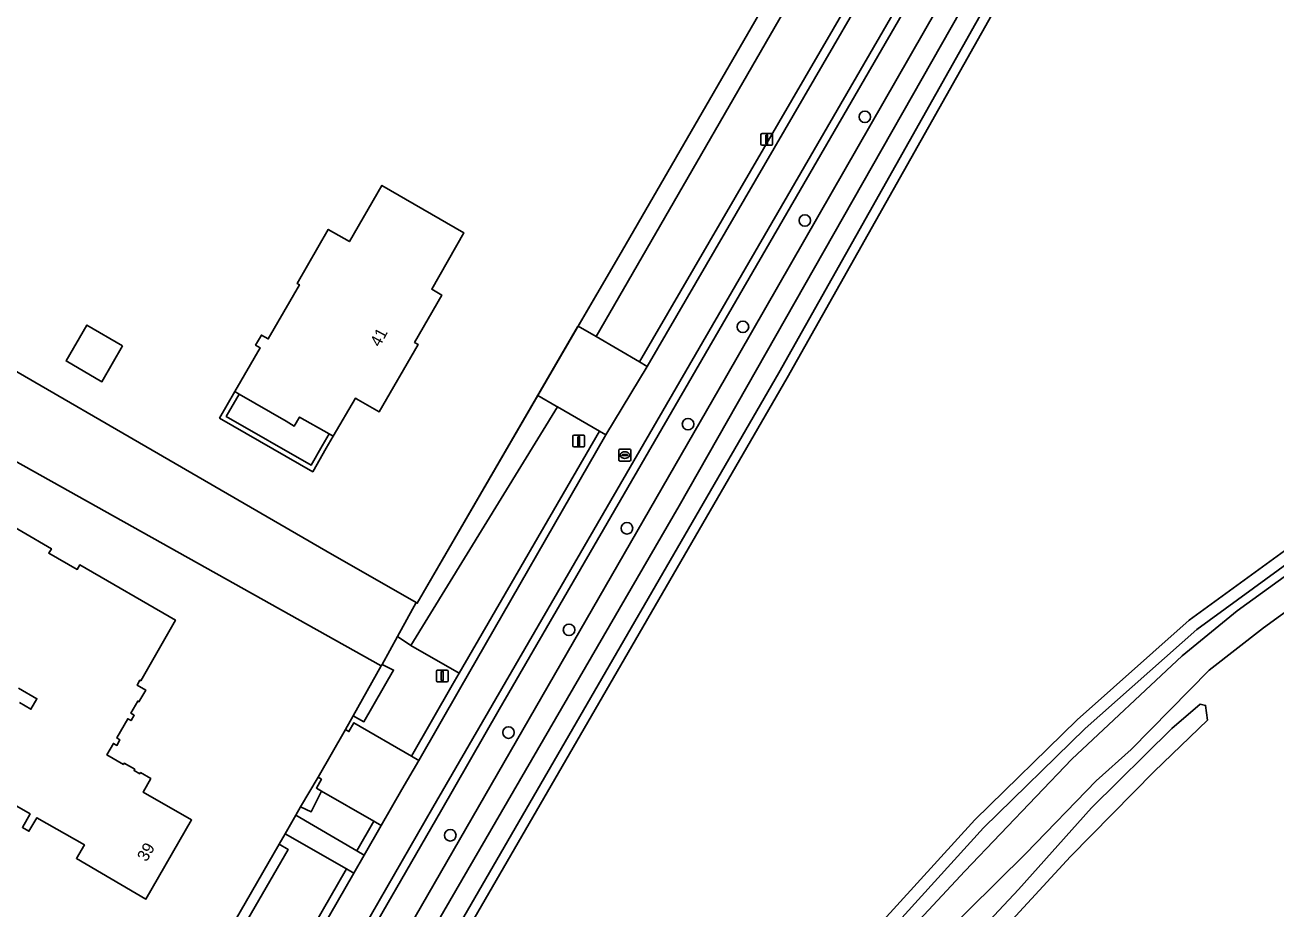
# Model space of a CAD drawing. Extents: x 156502 to 159075, y 384229 to 386100.
# Drawn here: x 157270.5 to 157376.3, y 385705.1 to 385779.8 of the extents above; entities that cross this region are included whole.
import ezdxf

# ---------------------------------------------------------------- set-up
doc = ezdxf.new("R2010")
doc.units = 0
for name, color, linetype in [('IMGEO_Boom', 7, 'Continuous'), ('IMGEO_Erf', 7, 'Continuous'), ('IMGEO_Gemengd_bos', 7, 'Continuous'), ('IMGEO_Grasland_overig', 7, 'Continuous'), ('IMGEO_Greppel_droge_sloot', 7, 'Continuous'), ('IMGEO_Groenvoorziening', 7, 'Continuous'), ('IMGEO_Hek', 7, 'Continuous'), ('IMGEO_Lichtmast', 7, 'Continuous'), ('IMGEO_Muur', 7, 'Continuous'), ('IMGEO_Oever', 7, 'Continuous'), ('IMGEO_Pand', 7, 'Continuous'), ('IMGEO_Pand_nummerreeks', 7, 'Continuous'), ('IMGEO_Rijbaan_lokaal_halfverhard', 7, 'Continuous'), ('IMGEO_Rijbaan_lokaal_onverhard', 7, 'Continuous'), ('IMGEO_Rijbaan_lokaal_open', 7, 'Continuous'), ('IMGEO_Rioolput', 7, 'Continuous'), ('IMGEO_Voetpad_open', 7, 'Continuous'), ('IMGEO_Waterloop', 7, 'Continuous')]:
    doc.layers.add(name, color=color, linetype=linetype)

msp = doc.modelspace()

# ---------------------------------------------------------------- linework, layer by layer
at = {"layer": 'IMGEO_Boom'}
for centre in [(157341.53, 385772.07), (157336.45, 385763.3), (157331.21, 385754.3), (157326.57, 385746.07), (157321.4, 385737.26), (157316.5, 385728.67), (157311.38, 385719.98), (157306.45, 385711.29)]:
    msp.add_circle(centre, 0.489, dxfattribs=at)
at = {"layer": 'IMGEO_Erf'}
for points in [[(157260.44, 385826.72), (157272.04, 385820.04), (157275.52, 385818.05), (157285.22, 385812.46), (157254.63, 385759.26), (157295.91, 385735.36), (157303.57, 385730.97), (157303.66, 385730.92), (157313.86, 385748.5), (157317.18, 385754.23), (157317.26, 385754.36), (157320.72, 385760.25), (157337.11, 385788.6), (157340.4, 385794.34), (157345.49, 385803.19), (157347.71, 385807.02), (157370.69, 385846.65), (157370.74, 385846.77), (157371.55, 385848.55), (157374.53, 385855.11), (157336.95, 385876.45)], [(157268.67, 385670.14), (157291.96, 385710.53), (157292.48, 385711.42), (157293.37, 385712.99), (157293.78, 385713.69), (157295.26, 385716.2), (157297.59, 385720.23), (157298.24, 385721.4), (157300.61, 385725.63), (157250.89, 385753.43)], [(157267.66, 385738.45), (157272.7, 385735.53), (157272.48, 385735.15), (157274.88, 385733.78), (157275.1, 385734.16), (157283.19, 385729.49), (157280.26, 385724.37), (157280.18, 385724.41), (157279.95, 385724), (157280.68, 385723.58), (157280.11, 385722.58), (157280.01, 385722.64), (157279.42, 385721.62), (157279.71, 385721.45), (157279.44, 385720.99), (157279.16, 385721.15), (157278.23, 385719.52), (157278.5, 385719.36), (157278.24, 385718.89), (157277.95, 385719.06), (157277.39, 385718.09), (157278.79, 385717.29), (157278.85, 385717.39), (157279.75, 385716.87), (157279.69, 385716.77), (157280.18, 385716.49), (157280.24, 385716.59), (157281.11, 385716.09), (157280.46, 385714.94), (157284.56, 385712.59), (157280.7, 385705.9), (157274.81, 385709.33), (157275.49, 385710.48), (157271.47, 385712.78), (157270.8, 385711.63), (157270.24, 385711.96), (157270.9, 385713.1), (157266.2, 385715.79)], [(157270, 385722.51), (157270.96, 385721.95), (157271.48, 385722.84), (157269.92, 385723.74)]]:
    msp.add_lwpolyline(points, dxfattribs=at)
for points in [[(157290.36, 385752.54), (157289.98, 385752.76), (157290.47, 385753.61), (157291.05, 385753.28), (157293.69, 385757.86), (157293.49, 385757.98), (157296.12, 385762.54), (157297.92, 385761.51), (157300.66, 385766.27), (157307.61, 385762.25), (157304.88, 385757.48), (157305.73, 385756.99), (157303.43, 385752.99), (157303.72, 385752.82), (157300.42, 385747.11), (157298.66, 385748.13), (157298.42, 385748.26), (157296.54, 385745.04), (157295.96, 385744.03), (157294.81, 385742.04), (157286.93, 385746.58), (157288.22, 385748.82)], [(157278.72, 385752.69), (157276.97, 385749.66), (157273.94, 385751.42), (157275.7, 385754.45)], [(157287.5, 385746.73), (157294.67, 385742.59), (157295.61, 385744.23), (157296.19, 385745.24), (157293.7, 385746.67), (157293.25, 385745.91), (157292.55, 385746.32), (157288.58, 385748.61)]]:
    msp.add_lwpolyline(points, close=True, dxfattribs=at)
at = {"layer": 'IMGEO_Gemengd_bos'}
for points in [[(157458.7, 385822.57), (157423.67, 385843.01), (157401.01, 385856.04), (157400.45, 385856.36), (157400.33, 385856.13), (157400.02, 385856.3), (157396.13, 385858.5), (157395.47, 385857.33), (157372.59, 385816.74), (157334.96, 385750), (157287.88, 385668.68), (157271.39, 385640.19), (157191.03, 385500)], [(157313.88, 385657.2), (157319.42, 385669.46), (157326.38, 385682.33), (157329.75, 385687.46), (157336.36, 385696.35), (157342.79, 385703.77), (157350.84, 385712.61), (157359.49, 385721.05), (157368.98, 385729.49), (157384.16, 385740.55), (157398.32, 385750), (157403.23, 385753.28), (157414.47, 385760.23), (157425.48, 385766.09), (157436.74, 385770.62), (157451.12, 385774.84), (157465.72, 385778.54), (157474.31, 385780.52)], [(157474.54, 385779.54), (157465.96, 385777.56), (157451.38, 385773.86), (157437.07, 385769.66), (157425.91, 385765.18), (157414.97, 385759.35), (157403.77, 385752.43), (157400.13, 385750), (157384.74, 385739.73), (157369.61, 385728.71), (157360.18, 385720.32), (157351.57, 385711.91), (157343.55, 385703.1), (157337.15, 385695.72), (157330.58, 385686.89), (157327.25, 385681.81), (157320.32, 385669.01), (157314.81, 385656.81), (157309.55, 385643.22), (157304.76, 385626.85), (157289.94, 385563.14), (157287.02, 385552.69)], [(157307.36, 385633.66), (157308.77, 385638.36), (157313.72, 385652.7), (157315.99, 385658.02), (157324.09, 385675.08), (157328.32, 385682.73), (157330.69, 385686.32), (157335.38, 385692.58), (157350, 385708.26), (157359.05, 385717.74), (157368.37, 385726.47), (157373.02, 385730.27), (157388.24, 385741.27), (157401.41, 385750), (157406.16, 385753.14), (157410.79, 385755.97), (157420.02, 385761.13), (157420.89, 385761.55), (157433.84, 385766.77), (157439.68, 385768.72), (157452.62, 385772.03)]]:
    msp.add_lwpolyline(points, dxfattribs=at)
msp.add_lwpolyline([(157285.22, 385812.46), (157275.52, 385818.05), (157272.04, 385820.04), (157246.93, 385776.79), (157242.96, 385769.96), (157222.97, 385734.27), (157232.44, 385728.12), (157250.89, 385753.43), (157300.61, 385725.63), (157300.68, 385725.75), (157301.99, 385728.11), (157303.57, 385730.97), (157295.91, 385735.36), (157254.63, 385759.26)], close=True, dxfattribs=at)
at = {"layer": 'IMGEO_Grasland_overig'}
for points in [[(157385.01, 385735.91), (157375.26, 385728.85), (157370.65, 385725.25), (157364.06, 385718.55), (157361.1, 385715.9), (157355.14, 385709.74), (157340.46, 385695.22), (157338.44, 385692.86), (157335.57, 385689), (157332.67, 385684.44), (157330.34, 385679.68), (157328.02, 385675.4), (157323.45, 385668.06), (157321.88, 385665.22), (157317.27, 385655), (157315.24, 385649.68), (157313.24, 385643.86), (157311.39, 385637.62), (157309.76, 385633.05)], [(157320.16, 385654.3), (157326.49, 385667.85), (157329.13, 385673.02), (157336.2, 385684.73), (157342.72, 385693.77), (157347.46, 385699.15), (157354.54, 385706.7), (157360.71, 385713.62), (157367.5, 385720.32), (157369.9, 385722.39), (157370.36, 385722.27), (157370.53, 385721.03), (157366.02, 385716.7), (157358.94, 385709.5), (157353.97, 385704.1), (157342.4, 385690.74)]]:
    msp.add_lwpolyline(points, dxfattribs=at)
at = {"layer": 'IMGEO_Greppel_droge_sloot'}
for points in [[(157393.36, 385858.05), (157393.11, 385857.61), (157362.75, 385804.11), (157325.82, 385739.17), (157293.92, 385684.22), (157277.51, 385655.56), (157259.26, 385623.71), (157238.62, 385587.75), (157224.85, 385563.79), (157203.07, 385525.9), (157174.27, 385475.36), (157161.25, 385452.05), (157151.08, 385433.93), (157146.7, 385427.27), (157144.86, 385424.97)], [(157146.46, 385424.36), (157148.98, 385428.05), (157150.58, 385430.99), (157151.89, 385433.4), (157190.31, 385500.41), (157270.67, 385640.6), (157287.16, 385669.09), (157334.24, 385750.41), (157371.86, 385817.15), (157394.6, 385857.47)]]:
    msp.add_lwpolyline(points, dxfattribs=at)
at = {"layer": 'IMGEO_Groenvoorziening'}
for points in [[(157395.47, 385857.33), (157396.13, 385858.5), (157400.02, 385856.3), (157400.33, 385856.13), (157400.45, 385856.36), (157394.87, 385860.03), (157394.47, 385860.19), (157394.07, 385860.35), (157391.83, 385861.67), (157349.52, 385789.09), (157310.6, 385721.93), (157305.61, 385713.27), (157297.81, 385699.74), (157287.9, 385682.57), (157281.97, 385672.23), (157284.2, 385670.89), (157329.73, 385750)], [(157329.73, 385750), (157392.25, 385858.97)]]:
    msp.add_lwpolyline(points, dxfattribs=at)
for points in [[(157338.56, 385787.75), (157337.11, 385788.6), (157320.72, 385760.25), (157317.26, 385754.36), (157318.78, 385753.48)], [(157342.35, 385785.53), (157338.56, 385787.75), (157318.78, 385753.48), (157322.45, 385751.34)], [(157315.53, 385747.53), (157315.4, 385747.6), (157313.86, 385748.5), (157303.66, 385730.92), (157303.57, 385730.97), (157301.99, 385728.11), (157303.1, 385727.35)], [(157319.08, 385745.47), (157315.53, 385747.53), (157303.1, 385727.35), (157307.21, 385725.01)], [(157306.6, 385723.98), (157307.21, 385725.01), (157303.1, 385727.35), (157301.99, 385728.11), (157300.68, 385725.75), (157301.65, 385725.27), (157299.14, 385720.9), (157298.24, 385721.4), (157297.59, 385720.23), (157297.87, 385720.06), (157298.3, 385720.81), (157303.16, 385717.99)], [(157300.68, 385725.75), (157300.61, 385725.63), (157298.24, 385721.4), (157299.14, 385720.9), (157301.65, 385725.27)], [(157295.56, 385715.03), (157295.12, 385715.29), (157295.54, 385716.03), (157295.26, 385716.2), (157293.78, 385713.69), (157294.67, 385713.27)], [(157295.56, 385715.03), (157294.67, 385713.27), (157293.78, 385713.69), (157293.37, 385712.99), (157298.55, 385709.98), (157299.99, 385712.48)], [(157293.66, 385701.48), (157297.66, 385708.44), (157292.48, 385711.42), (157291.96, 385710.53), (157292.73, 385710.1), (157269.35, 385669.72), (157270.11, 385669.25), (157268.64, 385666.52), (157272.3, 385664.39), (157273.57, 385666.58), (157284.33, 385685.27)], [(157291.96, 385710.53), (157268.67, 385670.14), (157269.35, 385669.72), (157292.73, 385710.1)]]:
    msp.add_lwpolyline(points, close=True, dxfattribs=at)
at = {"layer": 'IMGEO_Hek'}
for points in [[(157334.96, 385750), (157372.59, 385816.74)], [(157295.91, 385735.36), (157254.63, 385759.26), (157285.22, 385812.46)], [(157320.72, 385760.25), (157337.11, 385788.6)], [(157320.72, 385760.25), (157317.18, 385754.23)], [(157303.57, 385730.97), (157303.66, 385730.92), (157317.21, 385754.31)], [(157334.96, 385750), (157287.88, 385668.68)], [(157295.91, 385735.36), (157303.57, 385730.97)]]:
    msp.add_lwpolyline(points, dxfattribs=at)
at = {"layer": 'IMGEO_Lichtmast'}
for p, q in [((157332.73, 385769.76), (157332.73, 385770.55)), ((157332.73, 385770.55), (157332.73, 385769.76)), ((157332.83, 385770.65), (157333.62, 385770.65)), ((157333.62, 385770.65), (157332.83, 385770.65)), ((157333.72, 385770.55), (157333.72, 385769.76)), ((157333.72, 385769.76), (157333.72, 385770.55)), ((157333.62, 385769.66), (157332.83, 385769.66)), ((157332.83, 385769.66), (157333.62, 385769.66)), ((157316.82, 385744.24), (157316.82, 385745.04)), ((157316.82, 385745.04), (157316.82, 385744.24)), ((157316.92, 385745.14), (157317.71, 385745.14)), ((157317.71, 385745.14), (157316.92, 385745.14)), ((157317.81, 385745.04), (157317.81, 385744.24)), ((157317.81, 385744.24), (157317.81, 385745.04)), ((157317.71, 385744.14), (157316.92, 385744.14)), ((157316.92, 385744.14), (157317.71, 385744.14)), ((157305.38, 385725.27), (157306.16, 385725.27)), ((157306.16, 385725.27), (157305.38, 385725.27)), ((157305.28, 385724.37), (157305.28, 385725.17)), ((157305.28, 385725.17), (157305.28, 385724.37)), ((157306.16, 385724.27), (157305.38, 385724.27)), ((157305.38, 385724.27), (157306.16, 385724.27)), ((157306.26, 385725.17), (157306.26, 385724.37)), ((157306.26, 385724.37), (157306.26, 385725.17))]:
    msp.add_line(p, q, dxfattribs=at)
for points in [[(157333.15, 385770.53), (157333.3, 385770.53), (157333.3, 385769.78), (157333.15, 385769.78), (157333.15, 385770.53)], [(157317.24, 385745.01), (157317.39, 385745.01), (157317.39, 385744.26), (157317.24, 385744.26), (157317.24, 385745.01)], [(157305.69, 385725.14), (157305.85, 385725.14), (157305.85, 385724.39), (157305.69, 385724.39), (157305.69, 385725.14)]]:
    msp.add_lwpolyline(points, dxfattribs=at)
for centre, start, end in [((157332.83, 385770.55), 90, 180), ((157332.83, 385770.55), 90, 180), ((157332.83, 385769.76), 180, 270), ((157332.83, 385769.76), 180, 270), ((157333.62, 385770.55), 0, 90), ((157333.62, 385770.55), 360, 90), ((157333.62, 385769.76), 270, 0), ((157333.62, 385769.76), 270, 0), ((157316.92, 385745.04), 90, 180), ((157316.92, 385745.04), 90, 180), ((157317.71, 385745.04), 0, 90), ((157317.71, 385745.04), 360, 90), ((157316.92, 385744.24), 180, 270), ((157316.92, 385744.24), 180, 270), ((157317.71, 385744.24), 270, 0), ((157317.71, 385744.24), 270, 0), ((157305.38, 385725.17), 90, 180), ((157305.38, 385725.17), 90, 180), ((157306.16, 385725.17), 0, 90), ((157306.16, 385725.17), 360, 90), ((157305.38, 385724.37), 180, 270), ((157305.38, 385724.37), 180, 270), ((157306.16, 385724.37), 270, 0), ((157306.16, 385724.37), 270, 0)]:
    msp.add_arc(centre, 0.1, start, end, dxfattribs=at)
at = {"layer": 'IMGEO_Muur'}
msp.add_lwpolyline([(157286.93, 385746.58), (157294.81, 385742.04), (157295.96, 385744.03), (157296.54, 385745.04), (157296.19, 385745.24), (157295.61, 385744.23), (157294.67, 385742.59), (157287.5, 385746.73), (157288.58, 385748.61), (157288.22, 385748.82)], close=True, dxfattribs=at)
at = {"layer": 'IMGEO_Oever'}
for points in [[(157392.25, 385858.97), (157329.73, 385750), (157284.2, 385670.89), (157172.1, 385476.13), (157169.19, 385471.06), (157144.41, 385428.01), (157142.39, 385426.07), (157140.63, 385424.94), (157139.2, 385424.57), (157138.03, 385424.77), (157136.95, 385425.17), (157066.81, 385467.26), (157031.92, 385488.2), (156971.45, 385524.49), (156960.96, 385531.06), (156958.28, 385532.65)], [(157144.86, 385424.97), (157146.7, 385427.27), (157151.08, 385433.93), (157161.25, 385452.05), (157174.27, 385475.36), (157203.07, 385525.9), (157224.85, 385563.79), (157238.62, 385587.75), (157259.26, 385623.71), (157277.51, 385655.56), (157293.92, 385684.22), (157325.82, 385739.17), (157362.75, 385804.11), (157393.11, 385857.61), (157393.36, 385858.05)], [(157146.17, 385421.74), (157150.67, 385429.59), (157152.55, 385432.88), (157191.03, 385500), (157271.39, 385640.19), (157287.88, 385668.68), (157334.96, 385750), (157372.59, 385816.74), (157395.47, 385857.33)], [(157394.6, 385857.47), (157371.86, 385817.15), (157334.24, 385750.41), (157287.16, 385669.09), (157270.67, 385640.6), (157190.31, 385500.41), (157151.89, 385433.4), (157150.58, 385430.99), (157148.98, 385428.05), (157146.46, 385424.36)]]:
    msp.add_lwpolyline(points, dxfattribs=at)
at = {"layer": 'IMGEO_Pand'}
for points in [[(157293.49, 385757.98), (157293.69, 385757.86), (157291.05, 385753.28), (157290.47, 385753.61), (157289.98, 385752.76), (157290.36, 385752.54), (157288.22, 385748.82), (157288.58, 385748.61), (157292.55, 385746.32), (157293.25, 385745.91), (157293.7, 385746.67), (157296.19, 385745.24), (157296.54, 385745.04), (157298.42, 385748.26), (157298.66, 385748.13), (157300.42, 385747.11), (157303.72, 385752.82), (157303.43, 385752.99), (157305.73, 385756.99), (157304.88, 385757.48), (157307.61, 385762.25), (157300.66, 385766.27), (157297.92, 385761.51), (157296.12, 385762.54)], [(157278.72, 385752.69), (157275.7, 385754.45), (157273.94, 385751.42), (157276.97, 385749.66)]]:
    msp.add_lwpolyline(points, close=True, dxfattribs=at)
for points in [[(157266.2, 385715.79), (157270.9, 385713.1), (157270.24, 385711.96), (157270.8, 385711.63), (157271.47, 385712.78), (157275.49, 385710.48), (157274.81, 385709.33), (157280.7, 385705.9), (157284.56, 385712.59), (157280.46, 385714.94), (157281.11, 385716.09), (157280.24, 385716.59), (157280.18, 385716.49), (157279.69, 385716.77), (157279.75, 385716.87), (157278.85, 385717.39), (157278.79, 385717.29), (157277.39, 385718.09), (157277.95, 385719.06), (157278.24, 385718.89), (157278.5, 385719.36), (157278.23, 385719.52), (157279.16, 385721.15), (157279.44, 385720.99), (157279.71, 385721.45), (157279.42, 385721.62), (157280.01, 385722.64), (157280.11, 385722.58), (157280.68, 385723.58), (157279.95, 385724), (157280.18, 385724.41), (157280.26, 385724.37), (157283.19, 385729.49), (157275.1, 385734.16), (157274.88, 385733.78), (157272.48, 385735.15), (157272.7, 385735.53), (157267.66, 385738.45)], [(157269.92, 385723.74), (157271.48, 385722.84), (157270.96, 385721.95), (157270, 385722.51)]]:
    msp.add_lwpolyline(points, dxfattribs=at)
at = {"layer": 'IMGEO_Rijbaan_lokaal_halfverhard'}
for points in [[(157349.52, 385789.09), (157348.91, 385789.44), (157309.98, 385722.29), (157304.98, 385713.63), (157297.19, 385700.1), (157287.28, 385682.93), (157276.98, 385664.99), (157272.99, 385658.15), (157259.7, 385634.92), (157260.02, 385634.73), (157260.32, 385634.56), (157273.62, 385657.79), (157277.6, 385664.64), (157281.97, 385672.23), (157287.9, 385682.57), (157297.81, 385699.74), (157305.61, 385713.27), (157310.6, 385721.93)], [(157342.98, 385785.16), (157342.35, 385785.53), (157322.45, 385751.34), (157323.12, 385750.95)], [(157319.61, 385745.16), (157319.08, 385745.47), (157307.21, 385725.01), (157306.6, 385723.98), (157303.16, 385717.99), (157303.78, 385717.63), (157307.23, 385723.61)], [(157300.61, 385712.13), (157299.99, 385712.48), (157298.55, 385709.98), (157299.17, 385709.62)], [(157298.29, 385708.09), (157297.66, 385708.44), (157293.66, 385701.48), (157284.33, 385685.27), (157273.57, 385666.58), (157272.3, 385664.39), (157272.92, 385664.02), (157274.19, 385666.22), (157284.95, 385684.91), (157294.28, 385701.12)]]:
    msp.add_lwpolyline(points, close=True, dxfattribs=at)
at = {"layer": 'IMGEO_Rijbaan_lokaal_onverhard'}
for points in [[(157452.62, 385772.03), (157439.68, 385768.72), (157433.84, 385766.77), (157420.89, 385761.55), (157420.02, 385761.13), (157410.79, 385755.97), (157406.16, 385753.14), (157401.41, 385750), (157388.24, 385741.27), (157373.02, 385730.27), (157368.37, 385726.47), (157359.05, 385717.74), (157350, 385708.26), (157335.38, 385692.58), (157330.69, 385686.32), (157328.32, 385682.73), (157324.09, 385675.08), (157315.99, 385658.02), (157313.72, 385652.7), (157308.77, 385638.36), (157307.36, 385633.66)], [(157309.76, 385633.05), (157311.39, 385637.62), (157313.24, 385643.86), (157315.24, 385649.68), (157317.27, 385655), (157321.88, 385665.22), (157323.45, 385668.06), (157328.02, 385675.4), (157330.34, 385679.68), (157332.67, 385684.44), (157335.57, 385689), (157338.44, 385692.86), (157340.46, 385695.22), (157355.14, 385709.74), (157361.1, 385715.9), (157364.06, 385718.55), (157370.65, 385725.25), (157375.26, 385728.85), (157385.01, 385735.91)]]:
    msp.add_lwpolyline(points, dxfattribs=at)
at = {"layer": 'IMGEO_Rijbaan_lokaal_open'}
for points in [[(157348.91, 385789.44), (157346.33, 385790.92), (157342.98, 385785.16), (157323.12, 385750.95), (157319.61, 385745.16), (157307.23, 385723.61), (157303.78, 385717.63), (157302.35, 385715.15), (157300.61, 385712.13), (157299.17, 385709.62), (157298.29, 385708.09), (157294.28, 385701.12), (157284.95, 385684.91), (157274.19, 385666.22), (157272.92, 385664.02), (157270.01, 385658.98), (157269.67, 385658.4), (157266.46, 385652.88), (157264.81, 385649.96)], [(157258.5, 385639.01), (157257.01, 385636.46), (157259.7, 385634.92), (157272.99, 385658.15), (157276.98, 385664.99), (157287.28, 385682.93), (157297.19, 385700.1), (157304.98, 385713.63), (157309.98, 385722.29), (157348.91, 385789.44)]]:
    msp.add_lwpolyline(points, dxfattribs=at)
for points in [[(157323.12, 385750.95), (157322.45, 385751.34), (157318.78, 385753.48), (157317.26, 385754.36), (157317.18, 385754.23), (157313.86, 385748.5), (157315.4, 385747.6), (157315.53, 385747.53), (157319.08, 385745.47), (157319.61, 385745.16)], [(157303.78, 385717.63), (157303.16, 385717.99), (157298.3, 385720.81), (157297.87, 385720.06), (157297.59, 385720.23), (157295.26, 385716.2), (157295.54, 385716.03), (157295.12, 385715.29), (157295.56, 385715.03), (157299.99, 385712.48), (157300.61, 385712.13), (157302.35, 385715.15)]]:
    msp.add_lwpolyline(points, close=True, dxfattribs=at)
at = {"layer": 'IMGEO_Rioolput'}
for p, q in [((157320.72, 385743.02), (157320.72, 385743.88)), ((157320.79, 385743.95), (157321.65, 385743.95)), ((157320.98, 385743.44), (157320.98, 385743.46)), ((157321.02, 385743.49), (157321.42, 385743.49)), ((157321.42, 385743.41), (157321.02, 385743.41)), ((157321.21, 385743.73), (157321.23, 385743.73)), ((157321.46, 385743.46), (157321.46, 385743.44)), ((157321.72, 385743.88), (157321.72, 385743.02)), ((157321.65, 385742.95), (157320.79, 385742.95)), ((157321.23, 385743.17), (157321.2, 385743.17))]:
    msp.add_line(p, q, dxfattribs=at)
for points in [[(157320.72, 385743.02), (157320.72, 385743.88)], [(157320.79, 385743.95), (157321.65, 385743.95)], [(157321.72, 385743.88), (157321.72, 385743.02)], [(157321.65, 385742.95), (157320.79, 385742.95)]]:
    msp.add_lwpolyline(points, dxfattribs=at)
for centre, radius, start, end in [((157320.8, 385743.87), 0.0765, 91.552, 178.448), ((157320.8, 385743.87), 0.0765, 91.552, 178.448), ((157321.02, 385743.45), 0.0403, 85.8775, 175.7526), ((157321.01, 385743.44), 0.0366, 178.938, 274.7102), ((157321.42, 385743.45), 0.0386, 1.7309, 96.639), ((157321.42, 385743.45), 0.043, 264.8664, 352.4533), ((157321.64, 385743.87), 0.0765, 1.552, 88.448), ((157321.64, 385743.87), 0.0765, 1.552, 88.448), ((157320.8, 385743.03), 0.0765, 181.552, 268.448), ((157320.8, 385743.03), 0.0765, 181.552, 268.448), ((157321.64, 385743.03), 0.0765, 271.552, 358.448), ((157321.64, 385743.03), 0.0765, 271.552, 358.448)]:
    msp.add_arc(centre, radius, start, end, dxfattribs=at)
for centre, major_axis, ratio, start_param, end_param in [((157321.21, 385743.45), (-0.387, 0.002), 0.722429, 4.712389, 7.853982), ((157321.23, 385743.45), (-0.39, 0.002), 0.717154, 1.570796, 4.712389)]:
    msp.add_ellipse(centre, major_axis=major_axis, ratio=ratio, start_param=start_param, end_param=end_param, dxfattribs=at)
at = {"layer": 'IMGEO_Voetpad_open'}
msp.add_lwpolyline([(157293.37, 385712.99), (157292.48, 385711.42), (157297.66, 385708.44), (157298.29, 385708.09), (157299.17, 385709.62), (157298.55, 385709.98)], close=True, dxfattribs=at)
at = {"layer": 'IMGEO_Waterloop'}
for points in [[(157474.31, 385780.52), (157465.72, 385778.54), (157451.12, 385774.84), (157436.74, 385770.62), (157425.48, 385766.09), (157414.47, 385760.23), (157403.23, 385753.28), (157398.32, 385750), (157384.16, 385740.55), (157368.98, 385729.49), (157359.49, 385721.05), (157350.84, 385712.61), (157342.79, 385703.77), (157336.36, 385696.35), (157329.75, 385687.46), (157326.38, 385682.33), (157319.42, 385669.46), (157313.88, 385657.2), (157308.6, 385643.55), (157303.79, 385627.1), (157288.96, 385563.39), (157286.05, 385552.96)], [(157287.02, 385552.69), (157289.94, 385563.14), (157304.76, 385626.85), (157309.55, 385643.22), (157314.81, 385656.81), (157320.32, 385669.01), (157327.25, 385681.81), (157330.58, 385686.89), (157337.15, 385695.72), (157343.55, 385703.1), (157351.57, 385711.91), (157360.18, 385720.32), (157369.61, 385728.71), (157384.74, 385739.73), (157400.13, 385750), (157403.77, 385752.43), (157414.97, 385759.35), (157425.91, 385765.18), (157437.07, 385769.66), (157451.38, 385773.86), (157465.96, 385777.56), (157474.54, 385779.54)], [(157321.6, 385654.27), (157325.2, 385662.22), (157329.74, 385671.15), (157332.88, 385676.81), (157337.57, 385684.25), (157342.4, 385690.74), (157353.97, 385704.1), (157358.94, 385709.5), (157366.02, 385716.7), (157370.53, 385721.03), (157370.36, 385722.27), (157369.9, 385722.39), (157367.5, 385720.32), (157360.71, 385713.62), (157354.54, 385706.7), (157347.46, 385699.15), (157342.72, 385693.77), (157336.2, 385684.73), (157329.13, 385673.02), (157326.49, 385667.85), (157320.16, 385654.3)]]:
    msp.add_lwpolyline(points, dxfattribs=at)

# ---------------------------------------------------------------- texts
at = {"layer": 'IMGEO_Pand_nummerreeks'}
for s, rotation, p in [('41', 61.6955, (157300.48, 385752.54)), ('39', 59.9772, (157280.75, 385708.99))]:
    msp.add_text(s, height=1, rotation=rotation, dxfattribs=at).set_placement(p)

doc.saveas('drawing.dxf')
